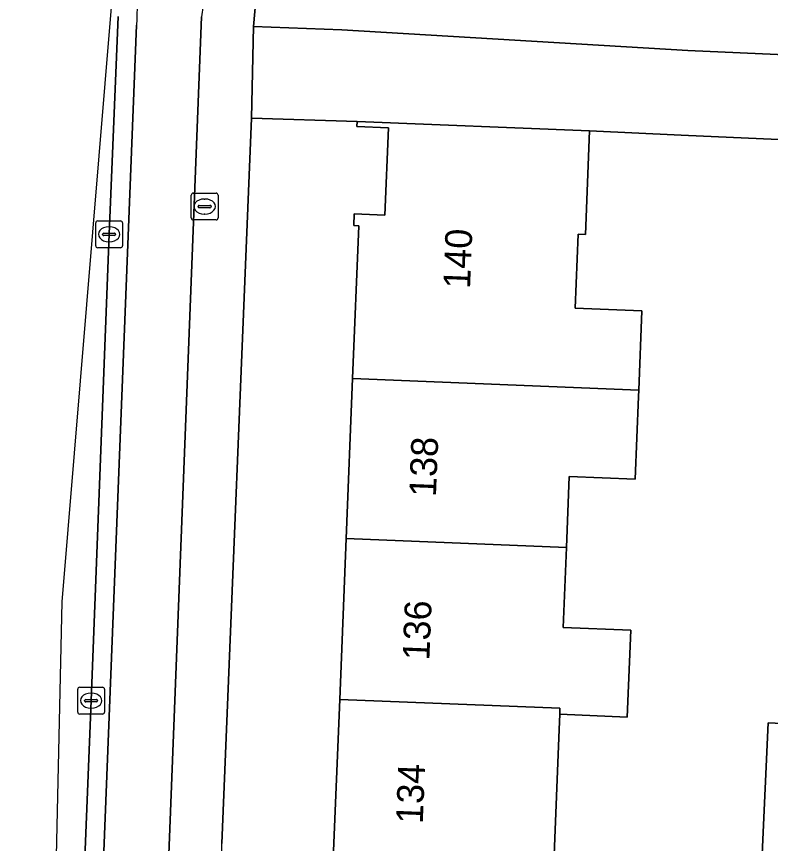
# Model space of a CAD drawing. Extents: x 161354 to 162026, y 386504 to 387460.
# Drawn here: x 161422.36 to 161450.47, y 387390.83 to 387421.67 of the extents above; entities that cross this region are included whole.
import ezdxf

# ---------------------------------------------------------------- set-up
doc = ezdxf.new("R2010")
doc.units = 0
for name, color, linetype in [('IMGEO_Berm_open', 7, 'Continuous'), ('IMGEO_Brandkraan', 7, 'Continuous'), ('IMGEO_Erf', 7, 'Continuous'), ('IMGEO_Fietspad_open', 7, 'Continuous'), ('IMGEO_Groenvoorziening', 7, 'Continuous'), ('IMGEO_Kolk', 7, 'Continuous'), ('IMGEO_Muur', 7, 'Continuous'), ('IMGEO_Pand', 7, 'Continuous'), ('IMGEO_Pand_nummerreeks', 7, 'Continuous'), ('IMGEO_Rijbaan_lokaal_gesloten', 7, 'Continuous'), ('IMGEO_Rijbaan_lokaal_open', 7, 'Continuous'), ('IMGEO_Voetpad_open', 7, 'Continuous')]:
    doc.layers.add(name, color=color, linetype=linetype)

msp = doc.modelspace()

# ---------------------------------------------------------------- linework, layer by layer
at = {"layer": 'IMGEO_Berm_open'}
for points in [[(161426.148, 387421.679), (161425.814, 387413.551), (161425.143, 387396.158), (161424.904, 387390.287), (161424.762, 387386.396), (161425.531, 387386.368)], [(161425.543, 387388.635), (161426.837, 387421.355)]]:
    msp.add_lwpolyline(points, dxfattribs=at)
msp.add_arc((161441.083, 387421.147), 14.247, 165.7969, 179.1645, dxfattribs=at)
at = {"layer": 'IMGEO_Brandkraan'}
for p, q in [((161428.948, 387415.086), (161429.8, 387415.086)), ((161428.873, 387414.16), (161428.873, 387415.012)), ((161429.361, 387414.866), (161429.386, 387414.866)), ((161429.874, 387415.012), (161429.874, 387414.16)), ((161429.132, 387414.58), (161429.132, 387414.592)), ((161429.57, 387414.543), (161429.172, 387414.543)), ((161429.175, 387414.629), (161429.573, 387414.629)), ((161429.616, 387414.592), (161429.616, 387414.58)), ((161429.384, 387414.306), (161429.359, 387414.306)), ((161429.8, 387414.086), (161428.948, 387414.086))]:
    msp.add_line(p, q, dxfattribs=at)
for points in [[(161428.948, 387415.086), (161429.8, 387415.086)], [(161428.873, 387414.16), (161428.873, 387415.012)], [(161429.874, 387415.012), (161429.874, 387414.16)], [(161429.8, 387414.086), (161428.948, 387414.086)]]:
    msp.add_lwpolyline(points, dxfattribs=at)
for centre, radius, start, end in [((161428.95, 387415.01), 0.0765, 91.552, 178.448), ((161428.95, 387415.01), 0.0765, 91.552, 178.448), ((161429.798, 387415.01), 0.0765, 1.552, 88.448), ((161429.798, 387415.01), 0.0765, 1.552, 88.448), ((161429.172, 387414.589), 0.0403, 85.8775, 175.7526), ((161429.169, 387414.579), 0.0366, 178.938, 274.7102), ((161429.573, 387414.586), 0.043, 264.8664, 352.4533), ((161429.577, 387414.591), 0.0386, 1.7309, 96.639), ((161428.95, 387414.162), 0.0765, 181.552, 268.448), ((161428.95, 387414.162), 0.0765, 181.552, 268.448), ((161429.798, 387414.162), 0.0765, 271.552, 358.448), ((161429.798, 387414.162), 0.0765, 271.552, 358.448)]:
    msp.add_arc(centre, radius, start, end, dxfattribs=at)
for centre, major_axis, ratio, start_param, end_param in [((161429.36, 387414.586), (-0.387, 0.002), 0.722429, 4.712389, 7.853982), ((161429.385, 387414.586), (-0.39, 0.002), 0.717154, 1.570796, 4.712389)]:
    msp.add_ellipse(centre, major_axis=major_axis, ratio=ratio, start_param=start_param, end_param=end_param, dxfattribs=at)
at = {"layer": 'IMGEO_Erf'}
for points in [[(161434.169, 387390.26), (161434.408, 387396.202), (161434.65, 387402.204), (161434.89, 387408.173), (161435.12, 387413.871), (161434.933, 387413.878), (161434.95, 387414.312), (161436.094, 387414.266), (161436.225, 387417.525), (161435.053, 387417.572), (161435.06, 387417.755), (161431.118, 387417.878), (161430.016, 387390.825)], [(161456.774, 387416.821), (161455.239, 387416.889), (161447.133, 387417.253), (161443.723, 387417.406), (161443.568, 387413.545), (161443.299, 387413.556), (161443.188, 387410.79), (161445.674, 387410.69), (161445.556, 387407.743), (161445.546, 387407.497), (161445.423, 387404.42), (161442.967, 387404.519), (161442.86, 387401.873), (161442.74, 387398.884), (161445.257, 387398.782), (161445.127, 387395.546), (161442.61, 387395.647), (161442.587, 387395.086), (161442.386, 387390.09)], [(161452.532, 387389.945), (161452.519, 387390.318), (161450.154, 387390.428), (161450.381, 387395.327), (161452.746, 387395.217), (161452.687, 387393.933), (161454.063, 387393.893), (161454.196, 387396.923), (161454.329, 387399.955), (161454.461, 387402.951), (161452.156, 387403.052), (161452.558, 387412.183)]]:
    msp.add_lwpolyline(points, dxfattribs=at)
at = {"layer": 'IMGEO_Fietspad_open'}
for points in [[(161427.986, 387389.15), (161429.262, 387421.666)], [(161426.837, 387421.355), (161425.543, 387388.635)]]:
    msp.add_lwpolyline(points, dxfattribs=at)
for centre, radius, start, end in [((161484.564, 387414.952), 55.708, 159.1757, 173.0775), ((161441.083, 387421.147), 14.247, 165.7969, 179.1645)]:
    msp.add_arc(centre, radius, start, end, dxfattribs=at)
at = {"layer": 'IMGEO_Groenvoorziening'}
msp.add_lwpolyline([(161431.421, 387423.443), (161431.294, 387422.429), (161431.197, 387421.295), (161434.484, 387421.175), (161447.383, 387420.409), (161462.724, 387419.725), (161464.073, 387419.511), (161500, 387417.889), (161529.101, 387416.63), (161529.424, 387423.439), (161529.46, 387424.501), (161503.74, 387425.354), (161499.222, 387425.612), (161479.57, 387426.734), (161461.822, 387427.873), (161462.206, 387432.775)], dxfattribs=at)
at = {"layer": 'IMGEO_Kolk'}
for p, q in [((161425.313, 387413.125), (161425.313, 387413.977)), ((161425.388, 387414.051), (161426.24, 387414.051)), ((161425.801, 387413.831), (161425.826, 387413.831)), ((161426.314, 387413.977), (161426.314, 387413.125)), ((161425.572, 387413.545), (161425.572, 387413.557)), ((161426.01, 387413.508), (161425.612, 387413.508)), ((161425.615, 387413.594), (161426.013, 387413.594)), ((161426.056, 387413.557), (161426.056, 387413.545)), ((161425.824, 387413.271), (161425.799, 387413.271)), ((161426.24, 387413.051), (161425.388, 387413.051)), ((161424.642, 387395.732), (161424.642, 387396.584)), ((161424.717, 387396.658), (161425.569, 387396.658)), ((161425.643, 387396.584), (161425.643, 387395.732)), ((161425.13, 387396.438), (161425.155, 387396.438)), ((161424.901, 387396.152), (161424.901, 387396.164)), ((161425.339, 387396.115), (161424.941, 387396.115)), ((161424.944, 387396.201), (161425.342, 387396.201)), ((161425.385, 387396.164), (161425.385, 387396.152)), ((161425.569, 387395.658), (161424.717, 387395.658)), ((161425.153, 387395.878), (161425.128, 387395.878))]:
    msp.add_line(p, q, dxfattribs=at)
for points in [[(161425.313, 387413.125), (161425.313, 387413.977)], [(161425.388, 387414.051), (161426.24, 387414.051)], [(161426.314, 387413.977), (161426.314, 387413.125)], [(161426.24, 387413.051), (161425.388, 387413.051)], [(161424.642, 387395.732), (161424.642, 387396.584)], [(161424.717, 387396.658), (161425.569, 387396.658)], [(161425.643, 387396.584), (161425.643, 387395.732)], [(161425.569, 387395.658), (161424.717, 387395.658)]]:
    msp.add_lwpolyline(points, dxfattribs=at)
for centre, radius, start, end in [((161425.39, 387413.975), 0.0765, 91.552, 178.448), ((161425.39, 387413.975), 0.0765, 91.552, 178.448), ((161426.238, 387413.975), 0.0765, 1.552, 88.448), ((161426.238, 387413.975), 0.0765, 1.552, 88.448), ((161425.612, 387413.554), 0.0403, 85.8775, 175.7526), ((161425.609, 387413.544), 0.0366, 178.938, 274.7102), ((161426.013, 387413.551), 0.043, 264.8664, 352.4533), ((161426.017, 387413.556), 0.0386, 1.7309, 96.639), ((161425.39, 387413.127), 0.0765, 181.552, 268.448), ((161425.39, 387413.127), 0.0765, 181.552, 268.448), ((161426.238, 387413.127), 0.0765, 271.552, 358.448), ((161426.238, 387413.127), 0.0765, 271.552, 358.448), ((161424.719, 387396.582), 0.0765, 91.552, 178.448), ((161424.719, 387396.582), 0.0765, 91.552, 178.448), ((161425.567, 387396.582), 0.0765, 1.552, 88.448), ((161425.567, 387396.582), 0.0765, 1.552, 88.448), ((161424.941, 387396.161), 0.0403, 85.8775, 175.7526), ((161424.938, 387396.151), 0.0366, 178.938, 274.7102), ((161425.342, 387396.158), 0.043, 264.8664, 352.4533), ((161425.346, 387396.163), 0.0386, 1.7309, 96.639), ((161424.719, 387395.734), 0.0765, 181.552, 268.448), ((161424.719, 387395.734), 0.0765, 181.552, 268.448), ((161425.567, 387395.734), 0.0765, 271.552, 358.448), ((161425.567, 387395.734), 0.0765, 271.552, 358.448)]:
    msp.add_arc(centre, radius, start, end, dxfattribs=at)
for centre, major_axis, ratio, start_param, end_param in [((161425.8, 387413.551), (-0.387, 0.002), 0.722429, 4.712389, 7.853982), ((161425.825, 387413.551), (-0.39, 0.002), 0.717154, 1.570796, 4.712389), ((161425.129, 387396.158), (-0.387, 0.002), 0.722429, 4.712389, 7.853982), ((161425.154, 387396.158), (-0.39, 0.002), 0.717154, 1.570796, 4.712389)]:
    msp.add_ellipse(centre, major_axis=major_axis, ratio=ratio, start_param=start_param, end_param=end_param, dxfattribs=at)
at = {"layer": 'IMGEO_Muur'}
msp.add_lwpolyline([(161443.723, 387417.406), (161447.133, 387417.253)], dxfattribs=at)
at = {"layer": 'IMGEO_Pand'}
for points in [[(161435.06, 387417.755), (161435.053, 387417.572), (161436.225, 387417.525), (161436.094, 387414.266), (161434.95, 387414.312), (161434.933, 387413.878), (161435.12, 387413.871), (161434.89, 387408.173), (161445.556, 387407.743), (161445.674, 387410.69), (161443.188, 387410.79), (161443.299, 387413.556), (161443.568, 387413.545), (161443.723, 387417.406)], [(161434.89, 387408.173), (161434.65, 387402.204), (161442.86, 387401.873), (161442.967, 387404.519), (161445.423, 387404.42), (161445.546, 387407.497), (161445.556, 387407.743)], [(161442.86, 387401.873), (161434.65, 387402.204), (161434.408, 387396.202), (161442.619, 387395.871), (161442.61, 387395.647), (161445.127, 387395.546), (161445.257, 387398.782), (161442.74, 387398.884)], [(161442.587, 387395.086), (161442.61, 387395.647), (161442.619, 387395.871), (161434.408, 387396.202), (161434.169, 387390.26), (161433.918, 387390.27), (161433.904, 387389.932), (161442.588, 387389.583), (161442.608, 387390.081), (161442.386, 387390.09)], [(161452.687, 387393.933), (161452.746, 387395.217), (161450.381, 387395.327), (161450.154, 387390.428), (161452.519, 387390.318)]]:
    msp.add_lwpolyline(points, close=True, dxfattribs=at)
at = {"layer": 'IMGEO_Rijbaan_lokaal_gesloten'}
msp.add_lwpolyline([(161428.174, 387449.614), (161424.054, 387399.845), (161422.363, 387323.994), (161422.864, 387337.123), (161423.111, 387343.514), (161423.64, 387357.225), (161424.371, 387375.643), (161424.762, 387386.396), (161424.904, 387390.287), (161425.143, 387396.158), (161425.814, 387413.551), (161426.148, 387421.679)], dxfattribs=at)
at = {"layer": 'IMGEO_Rijbaan_lokaal_open'}
msp.add_lwpolyline([(161462.724, 387419.725), (161447.383, 387420.409), (161434.484, 387421.175), (161431.197, 387421.295), (161431.118, 387417.878), (161435.06, 387417.755), (161443.723, 387417.406), (161447.133, 387417.253), (161455.239, 387416.889)], dxfattribs=at)
at = {"layer": 'IMGEO_Voetpad_open'}
for points in [[(161430.193, 387382.625), (161429.941, 387384.962), (161429.933, 387385.039), (161430.017, 387390.667), (161430.016, 387390.825), (161431.118, 387417.878), (161431.197, 387421.295), (161431.294, 387422.429), (161431.421, 387423.443)], [(161429.262, 387421.666), (161427.986, 387389.15)]]:
    msp.add_lwpolyline(points, dxfattribs=at)
msp.add_arc((161484.564, 387414.952), 55.708, 159.1757, 173.0775, dxfattribs=at)

# ---------------------------------------------------------------- texts
at = {"layer": 'IMGEO_Pand_nummerreeks'}
for s, rotation, p in [('140', 87.6982, (161439.266, 387411.508)), ('138', 87.6935, (161437.995, 387403.746)), ('136', 87.6912, (161437.749, 387397.647)), ('134', 87.6912, (161437.504, 387391.551))]:
    msp.add_text(s, height=1, rotation=rotation, dxfattribs=at).set_placement(p)

doc.saveas('drawing.dxf')
